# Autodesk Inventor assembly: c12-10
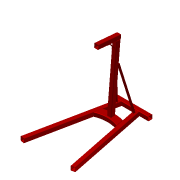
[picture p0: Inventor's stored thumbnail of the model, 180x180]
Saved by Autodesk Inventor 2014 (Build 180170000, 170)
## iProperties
Created: 2011-01
Part Number: c12-10
Document SubType Name: Assembly
Designer: Thom Tremblay
_SolveAssemblyDoc: Frame Generator Solve Assembly
_Version: 15.0.0
Author: Thom Tremblay
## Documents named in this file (3)
- C:\Inventor 2014 Essentials\Assemblies\Chapter 12\c12-10.iam
- C:\Inventor 2014 Essentials\Assemblies\Chapter 12\Frame\Frame c12-10.iam
- C:\Inventor 2014 Essentials\Parts\Chapter 12\c12-02.ipt
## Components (2 placed, 2 different names)
1. c12-02:1
2. Frame c12-10:1 [sub-assembly]
